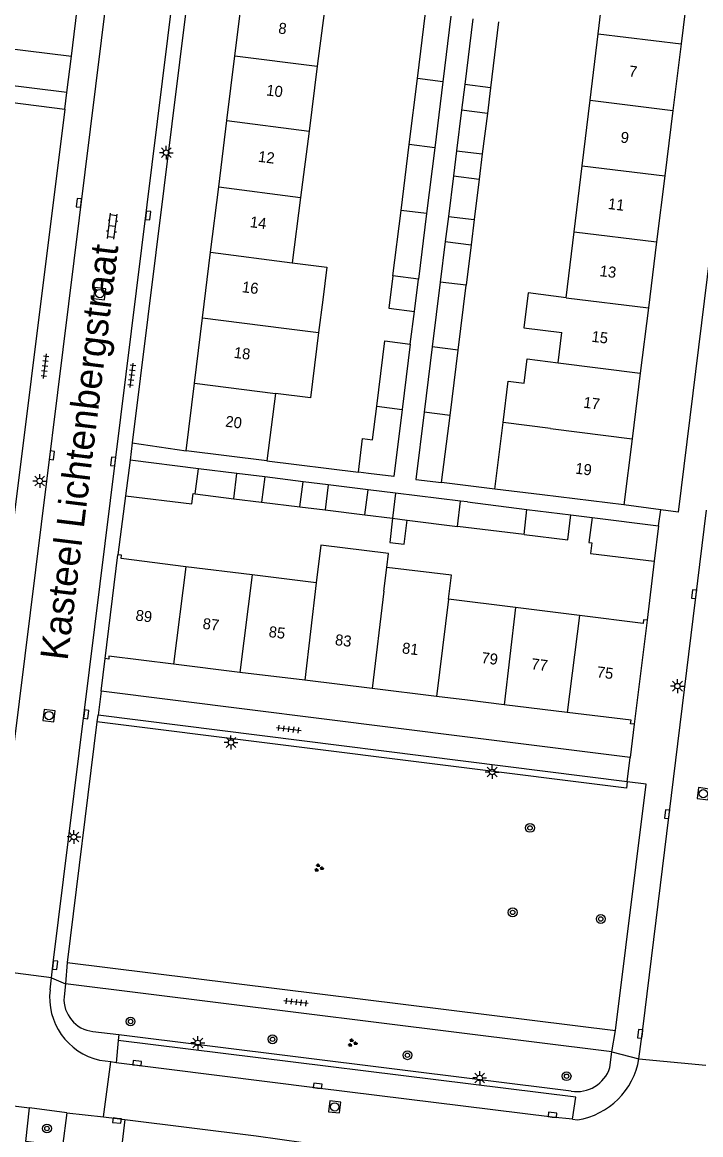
# Model space of a CAD drawing. Extents: x 131000 to 133014, y 396499 to 399001.
# Drawn here: x 131959.6 to 132021.2, y 396746.5 to 396847.4 of the extents above; entities that cross this region are included whole.
import ezdxf

# ---------------------------------------------------------------- set-up
doc = ezdxf.new("R2010")
doc.units = 0
for name, color, linetype in [('gg-afsc-erfafscheiding', 7, 'Continuous'), ('gg-afsc-muur', 7, 'Continuous'), ('gg-anno-huisnummerreeks BGT', 7, 'Continuous'), ('gg-anno-openbare ruimte label', 7, 'Continuous'), ('gg-bbg-bijgebouw', 7, 'Continuous'), ('gg-bbg-gedigitaliseerde bebouwing', 7, 'Continuous'), ('gg-bbg-gedigitaliseerde bijgebouw', 7, 'Continuous'), ('gg-bbg-hoofdgebouw', 7, 'Continuous'), ('gg-bbg-luifel en loopbrug', 7, 'Continuous'), ('gg-bbg-tussenscheiding', 7, 'Continuous'), ('gg-knt-verharding', 7, 'Continuous'), ('gg-knt-verharding nz', 7, 'Continuous'), ('gt-grn-groengrens', 7, 'Continuous'), ('gt-grn-weggrens', 7, 'Continuous'), ('gt-symb-boom', 7, 'Continuous'), ('gt-symb-groenvak', 7, 'Continuous'), ('gt-symb-klinker verharding', 7, 'Continuous'), ('gt-symb-kolk', 7, 'Continuous'), ('gt-symb-lichtmast', 7, 'Continuous'), ('gt-symb-rioolschacht', 7, 'Continuous'), ('gt-symb-tegel verharding', 7, 'Continuous')]:
    doc.layers.add(name, color=color, linetype=linetype)

# ---------------------------------------------------------------- blocks, each defined once
blk = doc.blocks.new('gt0-KOLK')
at = {"layer": 'gt-symb-kolk'}
blk.add_lwpolyline([(0, 0), (0.38, 0), (0.38, 0.4), (-0.38, 0.4), (-0.38, 0), (0, 0)], dxfattribs=at)
blk = doc.blocks.new('gt0-BOOM')
at = {"layer": 'gt-symb-boom'}
for radius in [0.4, 0.2]:
    blk.add_circle((0, 0), radius, dxfattribs=at)
blk = doc.blocks.new('gt0-LMAST')
at = {"layer": 'gt-symb-lichtmast'}
for p, q in [((-0.18, 0.17), (-0.45, 0.44)), ((-0.01, 0.25), (-0.01, 0.62)), ((0.17, 0.17), (0.44, 0.44)), ((-0.26, 0), (-0.63, 0)), ((-0.18, -0.18), (-0.45, -0.45)), ((-0.01, -0.25), (-0.01, -0.63)), ((0.44, -0.45), (0.17, -0.18)), ((0.24, 0), (0.62, 0))]:
    blk.add_line(p, q, dxfattribs=at)
blk.add_circle((-0.01, 0), 0.25, dxfattribs=at)
blk = doc.blocks.new('gt0-RS')
at = {"layer": 'gt-symb-rioolschacht'}
blk.add_lwpolyline([(-0.5, -0.5), (0.5, -0.5), (0.5, 0.5), (-0.5, 0.5)], close=True, dxfattribs=at)
blk.add_circle((0, 0), 0.375, dxfattribs=at)
blk = doc.blocks.new('gt0-TEG1')
at = {"layer": 'gt-symb-tegel verharding'}
for p, q in [((-1.12, 0), (1.12, 0)), ((-0.9, -0.25), (-0.9, 0.25)), ((-0.45, -0.25), (-0.45, 0.25)), ((0, -0.25), (0, 0.25)), ((0.45, -0.25), (0.45, 0.25)), ((0.9, -0.25), (0.9, 0.25))]:
    blk.add_line(p, q, dxfattribs=at)
blk = doc.blocks.new('gt0-GRVAK')
at = {"layer": 'gt-symb-groenvak'}
for p, q in [((-0.11, 0.19), (-0.23, 0.24)), ((-0.18, 0.15), (0.09, 0.15)), ((-0.09, 0.21), (-0.16, 0.32)), ((-0.05, 0.21), (-0.05, 0.39)), ((0, 0.21), (0.06, 0.32)), ((0.02, 0.19), (0.13, 0.24)), ((0.26, -0.05), (0.2, 0.06)), ((0.3, -0.05), (0.3, 0.13)), ((0.35, -0.05), (0.41, 0.06)), ((-0.24, -0.23), (-0.36, -0.18)), ((-0.32, -0.26), (-0.05, -0.26)), ((-0.23, -0.21), (-0.29, -0.09)), ((-0.18, -0.2), (-0.18, -0.02)), ((-0.14, -0.21), (-0.07, -0.09)), ((-0.12, -0.23), (0, -0.18)), ((0.24, -0.07), (0.12, -0.02)), ((0.17, -0.11), (0.44, -0.11)), ((0.37, -0.07), (0.49, -0.02))]:
    blk.add_line(p, q, dxfattribs=at)
blk = doc.blocks.new('gt0-KL1')
at = {"layer": 'gt-symb-klinker verharding'}
for p, q in [((-1.15, 0.3), (1.15, 0.3)), ((-1, -0.3), (-1, 0.3)), ((-0.5, 0.3), (-0.5, 0.45)), ((0, -0.3), (0, 0.3)), ((0.5, 0.3), (0.5, 0.45)), ((1, -0.3), (1, 0.3)), ((-1.15, -0.3), (1.15, -0.3)), ((-0.5, -0.45), (-0.5, -0.3)), ((0.5, -0.45), (0.5, -0.3))]:
    blk.add_line(p, q, dxfattribs=at)

msp = doc.modelspace()

# ---------------------------------------------------------------- linework, layer by layer
at = {"layer": 'gg-afsc-erfafscheiding'}
for p, q in [((131994.82, 396818.22), (131995.19, 396821.17)), ((131981.82, 396807.63), (131990.12, 396806.6)), ((132002.49, 396805.07), (131997.66, 396805.66)), ((132009.38, 396802.73), (132011.31, 396802.49))]:
    msp.add_line(p, q, dxfattribs=at)
at = {"layer": 'gg-afsc-muur'}
for p, q in [((131964.09, 396844.34), (131964.75, 396849.58)), ((131969, 396804.47), (131968.32, 396799.11)), ((132016.93, 396798.53), (132016.28, 396793.17))]:
    msp.add_line(p, q, dxfattribs=at)
at = {"layer": 'gg-bbg-bijgebouw'}
for p, q in [((131963.69, 396841.03), (131964.09, 396844.34)), ((131963.69, 396841.03), (131957.56, 396841.79)), ((131969.41, 396807.68), (131969, 396804.47)), ((131975.61, 396806.91), (131969.41, 396807.68)), ((131979.1, 396806.48), (131975.61, 396806.91)), ((131985.1, 396805.74), (131981.63, 396806.17)), ((131990.99, 396805.01), (131987.37, 396805.46)), ((131999.36, 396803.97), (131993.49, 396804.7)), ((132000, 396803.9), (131999.36, 396803.97)), ((132000, 396803.9), (132005.39, 396803.23)), ((132005.39, 396803.23), (132009.38, 396802.73)), ((132011.31, 396802.49), (132017.33, 396801.75)), ((132017.33, 396801.75), (132016.93, 396798.53))]:
    msp.add_line(p, q, dxfattribs=at)
at = {"layer": 'gg-bbg-gedigitaliseerde bebouwing'}
for p, q in [((132011.85, 396846.35), (132012.57, 396852.26)), ((131987.15, 396849.41), (131986.39, 396843.43)), ((132011.12, 396840.35), (132011.85, 396846.35)), ((131986.39, 396843.43), (131985.64, 396837.52)), ((132010.4, 396834.38), (132011.12, 396840.35)), ((131985.64, 396837.52), (131984.87, 396831.52)), ((132009.68, 396828.4), (132010.4, 396834.38)), ((131984.87, 396831.52), (131984.11, 396825.6)), ((132008.96, 396822.43), (132009.68, 396828.4)), ((131986.89, 396822.23), (131986.51, 396819.26)), ((132008.24, 396816.53), (132008.57, 396819.27)), ((131982.6, 396813.75), (131981.82, 396807.63)), ((132002.49, 396805.07), (132003.24, 396811.12)), ((131981.82, 396807.63), (131974.49, 396808.54)), ((132006.79, 396804.54), (132002.49, 396805.07)), ((132014.19, 396803.63), (132006.79, 396804.54)), ((131974.47, 396798.03), (131968.6, 396798.76)), ((131980.49, 396797.29), (131974.47, 396798.03)), ((131986.3, 396796.56), (131980.49, 396797.29)), ((132004.35, 396794.33), (131998.28, 396795.08)), ((132010.17, 396793.6), (132004.35, 396794.33)), ((132015.92, 396792.89), (132010.17, 396793.6))]:
    msp.add_line(p, q, dxfattribs=at)
for points in [[(131984.11, 396825.6), (131987.26, 396825.21), (131986.89, 396822.23)], [(132008.96, 396822.43), (132005.5, 396822.86), (132005.1, 396819.7), (132008.57, 396819.27)], [(131986.51, 396819.26), (131985.76, 396813.35), (131982.6, 396813.75)], [(132003.24, 396811.12), (132003.7, 396814.87), (132005.15, 396814.69), (132005.41, 396816.88), (132008.24, 396816.53)], [(131992.69, 396797.97), (131992.84, 396799.24), (131986.72, 396799.98), (131986.3, 396796.56)], [(131998.28, 396795.08), (131998.55, 396797.25), (131992.69, 396797.97)]]:
    msp.add_lwpolyline(points, dxfattribs=at)
at = {"layer": 'gg-bbg-gedigitaliseerde bijgebouw'}
for p, q in [((131995.46, 396842.3), (131996.19, 396848.26)), ((131998.51, 396847.96), (131997.77, 396842.01)), ((132000.49, 396847.72), (131999.75, 396841.76)), ((132002.83, 396847.44), (132002.09, 396841.47)), ((131957.97, 396845.08), (131964.09, 396844.34)), ((131994.71, 396836.32), (131995.46, 396842.3)), ((131997.77, 396842.01), (131997.03, 396836.01)), ((132002.09, 396841.47), (131999.75, 396841.76)), ((131999.46, 396839.43), (131999.01, 396835.76)), ((132001.81, 396839.14), (131999.46, 396839.43)), ((132001.81, 396839.14), (132001.35, 396835.47)), ((131993.98, 396830.35), (131994.71, 396836.32)), ((131997.03, 396836.01), (131996.29, 396830.05)), ((131999.01, 396835.76), (132001.35, 396835.47)), ((131998.73, 396833.47), (131998.27, 396829.8)), ((131998.73, 396833.47), (132001.07, 396833.18)), ((132001.07, 396833.18), (132000.61, 396829.51)), ((131993.24, 396824.4), (131993.98, 396830.35)), ((131996.29, 396830.05), (131995.55, 396824.1)), ((131998.27, 396829.8), (132000.61, 396829.51)), ((131997.99, 396827.51), (131997.54, 396823.85)), ((131997.99, 396827.51), (132000.33, 396827.22)), ((132000.33, 396827.22), (131999.88, 396823.55)), ((131995.19, 396821.17), (131995.55, 396824.1)), ((131997.54, 396823.85), (131996.81, 396817.97)), ((131999.15, 396817.68), (131999.88, 396823.55)), ((131991.78, 396812.58), (131992.51, 396818.51)), ((131992.51, 396818.51), (131994.82, 396818.22)), ((131994.82, 396818.22), (131994.09, 396812.29)), ((131996.81, 396817.97), (131996.07, 396812.04)), ((131998.42, 396811.74), (131999.15, 396817.68)), ((131991.4, 396809.55), (131991.78, 396812.58)), ((131997.66, 396805.66), (131998.42, 396811.74)), ((131978.82, 396804.2), (131979.1, 396806.48)), ((131991.02, 396806.49), (131990.12, 396806.6)), ((131981.63, 396806.17), (131981.34, 396803.89)), ((131984.82, 396803.46), (131985.1, 396805.74)), ((131987.37, 396805.46), (131987.09, 396803.18)), ((131975.32, 396804.64), (131978.82, 396804.2)), ((131990.7, 396802.73), (131990.99, 396805.01)), ((131993.49, 396804.7), (131993.22, 396802.42)), ((131981.34, 396803.89), (131984.82, 396803.46)), ((131987.09, 396803.18), (131990.7, 396802.73)), ((131993.22, 396802.42), (131994.55, 396802.26)), ((132011.31, 396802.49), (132011.02, 396800.22)), ((131994.55, 396802.26), (131999.09, 396801.69)), ((132005.13, 396800.95), (131999.09, 396801.69))]:
    msp.add_line(p, q, dxfattribs=at)
for points in [[(131993.24, 396824.4), (131992.88, 396821.47), (131995.19, 396821.17)], [(131994.09, 396812.29), (131993.33, 396806.2), (131991.02, 396806.49)], [(131996.07, 396812.04), (131995.32, 396805.95), (131997.66, 396805.66)], [(131990.12, 396806.6), (131990.5, 396809.66), (131991.4, 396809.55)], [(131969, 396804.47), (131975.02, 396803.72), (131975.14, 396804.66), (131975.32, 396804.64)], [(132005.13, 396800.95), (132009.1, 396800.46), (132009.38, 396802.73)], [(132011.02, 396800.22), (132011.29, 396800.18), (132011.17, 396799.23), (132016.93, 396798.53)]]:
    msp.add_lwpolyline(points, dxfattribs=at)
at = {"layer": 'gg-bbg-hoofdgebouw'}
for p, q in [((132020.1, 396851.32), (132019.37, 396845.45)), ((131978.92, 396844.37), (131979.66, 396850.36)), ((132019.37, 396845.45), (132018.63, 396839.42)), ((131978.19, 396838.5), (131978.92, 396844.37)), ((132018.63, 396839.42), (132017.89, 396833.47)), ((131977.45, 396832.47), (131978.19, 396838.5)), ((132017.89, 396833.47), (132017.15, 396827.48)), ((131976.72, 396826.57), (131977.45, 396832.47)), ((131975.98, 396820.6), (131976.72, 396826.57)), ((132017.15, 396827.48), (132016.41, 396821.51)), ((132016.41, 396821.51), (132015.67, 396815.59)), ((131975.25, 396814.68), (131975.98, 396820.6)), ((132015.67, 396815.59), (132014.93, 396809.62)), ((131974.49, 396808.54), (131975.25, 396814.68)), ((132014.93, 396809.62), (132014.19, 396803.63)), ((131967.16, 396789.69), (131968.32, 396799.11)), ((132016.28, 396793.17), (132015.11, 396783.74)), ((131979.36, 396788.45), (131973.34, 396789.19)), ((131985.25, 396787.73), (131979.36, 396788.45)), ((131991.37, 396786.98), (131985.25, 396787.73)), ((131997.21, 396786.26), (131991.37, 396786.98)), ((132000, 396785.92), (131997.21, 396786.26)), ((132003.32, 396785.51), (132000, 396785.92)), ((132009.04, 396784.81), (132003.32, 396785.51))]:
    msp.add_line(p, q, dxfattribs=at)
for points in [[(131968.6, 396798.76), (131968.64, 396799.07), (131968.32, 396799.11)], [(132016.28, 396793.17), (132015.96, 396793.21), (132015.92, 396792.89)], [(131973.34, 396789.19), (131967.5, 396789.91), (131967.48, 396789.65), (131967.16, 396789.69)], [(132015.11, 396783.74), (132014.79, 396783.78), (132014.83, 396784.1), (132009.04, 396784.81)]]:
    msp.add_lwpolyline(points, dxfattribs=at)
at = {"layer": 'gg-bbg-luifel en loopbrug'}
for p, q in [((131999.75, 396841.76), (131999.46, 396839.43)), ((132002.09, 396841.47), (132001.81, 396839.14)), ((131999.01, 396835.76), (131998.73, 396833.47)), ((132001.35, 396835.47), (132001.07, 396833.18)), ((131998.27, 396829.8), (131997.99, 396827.51)), ((132000.61, 396829.51), (132000.33, 396827.22)), ((131981.63, 396806.17), (131979.1, 396806.48)), ((131987.37, 396805.46), (131985.1, 396805.74)), ((131993.49, 396804.7), (131990.99, 396805.01)), ((131978.82, 396804.2), (131981.34, 396803.89)), ((131984.82, 396803.46), (131987.09, 396803.18)), ((131990.7, 396802.73), (131993.22, 396802.42))]:
    msp.add_line(p, q, dxfattribs=at)
msp.add_lwpolyline([(131993.22, 396802.42), (131992.95, 396800.22), (131994.27, 396800.06), (131994.55, 396802.26)], dxfattribs=at)
at = {"layer": 'gg-bbg-tussenscheiding'}
for p, q in [((132011.85, 396846.35), (132019.37, 396845.45)), ((131978.92, 396844.37), (131986.39, 396843.43)), ((131997.77, 396842.01), (131995.46, 396842.3)), ((132011.12, 396840.35), (132018.63, 396839.42)), ((131978.19, 396838.5), (131985.64, 396837.52)), ((131997.03, 396836.01), (131994.71, 396836.32)), ((132010.4, 396834.38), (132017.89, 396833.47)), ((131977.45, 396832.47), (131984.87, 396831.52)), ((131996.29, 396830.05), (131993.98, 396830.35)), ((132009.68, 396828.4), (132017.15, 396827.48)), ((131976.72, 396826.57), (131984.11, 396825.6)), ((131995.55, 396824.1), (131993.24, 396824.4)), ((131999.88, 396823.55), (131997.54, 396823.85)), ((132008.96, 396822.43), (132016.41, 396821.51)), ((131975.98, 396820.6), (131983.36, 396819.67)), ((131983.36, 396819.67), (131986.51, 396819.26)), ((131999.15, 396817.68), (131996.81, 396817.97)), ((132008.24, 396816.53), (132015.67, 396815.59)), ((131975.25, 396814.68), (131982.6, 396813.75)), ((131991.78, 396812.58), (131994.09, 396812.29)), ((131998.42, 396811.74), (131996.07, 396812.04)), ((132007.52, 396810.57), (132003.24, 396811.12)), ((132007.52, 396810.57), (132014.93, 396809.62)), ((131975.32, 396804.64), (131975.61, 396806.91)), ((131999.09, 396801.69), (131999.36, 396803.97)), ((132005.13, 396800.95), (132005.39, 396803.23)), ((131974.47, 396798.03), (131973.34, 396789.19)), ((131980.49, 396797.29), (131979.36, 396788.45)), ((131992.43, 396795.8), (131992.69, 396797.97)), ((131986.3, 396796.56), (131985.25, 396787.73)), ((131992.43, 396795.8), (131991.37, 396786.98)), ((131998.28, 396795.08), (131997.21, 396786.26)), ((132004.35, 396794.33), (132003.32, 396785.51)), ((132010.17, 396793.6), (132009.04, 396784.81))]:
    msp.add_line(p, q, dxfattribs=at)
at = {"layer": 'gg-knt-verharding'}
for p, q in [((131975.57, 396857.28), (131969.61, 396809.26)), ((131967.97, 396855.16), (131956.33, 396761.52)), ((131958.53, 396840.16), (131963.5, 396839.54)), ((131963.5, 396839.54), (131956.75, 396785.57)), ((131969.61, 396809.26), (131974.49, 396808.54)), ((132017.54, 396803.19), (132014.19, 396803.63)), ((131966.8, 396786.75), (131967.16, 396789.69)), ((132000, 396782.58), (131966.8, 396786.75)), ((132014.49, 396778.53), (131966.53, 396784.56)), ((131966.4, 396783.97), (131963.71, 396762.12)), ((132015.11, 396783.74), (132014.76, 396780.72)), ((132014.76, 396780.72), (132000, 396782.58)), ((131963.71, 396762.12), (132013.43, 396755.96)), ((131962.29, 396760.73), (131956.33, 396761.52)), ((131962.16, 396759.66), (131962.29, 396760.73)), ((131963.57, 396760.2), (131963.43, 396759.01)), ((132013.1, 396754.04), (131963.57, 396760.2)), ((131966.05, 396755.88), (131968.41, 396755.59)), ((131968.35, 396755.07), (131968.16, 396753.04)), ((131968.41, 396755.59), (132009.4, 396750.48)), ((132012.9, 396752.61), (132013.1, 396754.04)), ((131967.67, 396753.12), (131966.65, 396753.26)), ((131967.02, 396748.13), (131967.67, 396753.12)), ((131968.16, 396753.04), (131967.67, 396753.12)), ((131955.36, 396749.55), (131960.3, 396748.95)), ((131963.67, 396748.51), (131960.3, 396748.95)), ((131963.67, 396748.51), (131967.02, 396748.13)), ((132009.53, 396747.91), (132009.98, 396747.86))]:
    msp.add_line(p, q, dxfattribs=at)
for points in [[(132026.48, 396862.86), (132019.12, 396802.99), (132017.54, 396803.19)], [(131962.29, 396760.73), (131962.44, 396762.11), (131974.26, 396857.44)], [(132015.55, 396753.41), (132015.91, 396756.08), (132021.68, 396803.16)], [(131966.53, 396784.56), (131966.48, 396784.57), (131966.4, 396783.97)], [(132013.43, 396755.96), (132016.19, 396778.32), (132014.49, 396778.53)], [(132009.53, 396747.91), (132009.83, 396749.92), (131968.35, 396755.07)], [(131963.67, 396748.51), (131963.28, 396745.47), (131959.96, 396745.9), (131960.3, 396748.95)], [(131967.02, 396748.13), (131968.26, 396747.99), (131968.95, 396747.89)], [(131968.95, 396747.89), (131968.59, 396744.81), (131984.77, 396742.81), (131985.15, 396745.8)], [(131968.95, 396747.89), (131980.85, 396746.41), (131985.15, 396745.8)]]:
    msp.add_lwpolyline(points, dxfattribs=at)
for centre, radius, start, end in [((131967.96, 396758.96), 5.84, 173.1125, 257.0542), ((131966.38, 396758.82), 2.96, 176.2854, 263.5774), ((132008.9, 396754.51), 6.74, 279.2134, 350.5701), ((132009.95, 396753.52), 3.09, 259.8273, 342.9059)]:
    msp.add_arc(centre, radius, start, end, dxfattribs=at)
at = {"layer": 'gg-knt-verharding nz'}
msp.add_lwpolyline([(132009.53, 396747.91), (132007.69, 396748.12), (131986.4, 396750.75), (131968.16, 396753.04)], dxfattribs=at)
at = {"layer": 'gt-grn-groengrens'}
msp.add_lwpolyline([(132014.49, 396778.53), (132014.42, 396777.93), (131966.4, 396783.97)], dxfattribs=at)
at = {"layer": 'gt-grn-weggrens'}
for p, q in [((131963.5, 396839.54), (131963.69, 396841.03)), ((131969.61, 396809.26), (131969.41, 396807.68)), ((132017.33, 396801.75), (132017.54, 396803.19)), ((131966.8, 396786.75), (131966.53, 396784.56)), ((132014.49, 396778.53), (132014.76, 396780.72)), ((131963.71, 396762.12), (131963.57, 396760.2)), ((131962.29, 396760.73), (131963.57, 396760.2)), ((132013.1, 396754.04), (132013.43, 396755.96)), ((131968.41, 396755.59), (131968.35, 396755.07)), ((132013.1, 396754.04), (132015.55, 396753.41)), ((132015.55, 396753.41), (132021.61, 396752.83))]:
    msp.add_line(p, q, dxfattribs=at)

# ---------------------------------------------------------------- block references
at = {"layer": 'gt-symb-boom'}
for p in [(132005.67, 396774.34), (132004.1, 396766.68), (132012.09, 396766.08), (131969.46, 396756.78), (131982.33, 396755.17), (131994.56, 396753.72), (132008.99, 396751.82), (131961.88, 396747.08)]:
    msp.add_blockref('gt0-BOOM', p, dxfattribs=at)
at = {"layer": 'gt-symb-groenvak'}
for p in [(131986.52, 396770.71), (131989.56, 396754.85)]:
    msp.add_blockref('gt0-GRVAK', p, dxfattribs=at)
at = {"layer": 'gt-symb-klinker verharding', "rotation": 82.93185994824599}
msp.add_blockref('gt0-KL1', (131967.8, 396828.91), dxfattribs=at)
at = {"layer": 'gt-symb-kolk'}
for p, rotation in [((131964.97, 396831.01), 82.93185994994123), ((131970.85, 396829.91), -96.7767828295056), ((131962.13, 396808.15), -97.18187853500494), ((131968.07, 396807.55), 82.81812146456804), ((132020.75, 396795.52), 82.99574075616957), ((131965.24, 396784.67), -97.00425924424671), ((132018.3, 396775.56), 83.22321716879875), ((131962.42, 396761.92), -96.48566035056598), ((132015.86, 396755.64), 82.81812146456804), ((131970.03, 396752.81), -7.181878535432), ((131986.4, 396750.75), -7.068140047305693), ((131968.26, 396747.99), 173.45090842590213), ((132007.69, 396748.12), -6.428747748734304)]:
    msp.add_blockref('gt0-KOLK', p, dxfattribs=dict(at, rotation=rotation))
at = {"layer": 'gt-symb-lichtmast'}
for p in [(131972.7, 396835.58), (131961.23, 396805.8), (132019.05, 396787.2), (131978.57, 396782.09), (132002.25, 396779.41), (131964.33, 396773.52), (131975.56, 396754.84), (132001.12, 396751.66)]:
    msp.add_blockref('gt0-LMAST', p, dxfattribs=at)
at = {"layer": 'gt-symb-rioolschacht'}
for p, rotation in [((131966.67, 396822.8), -96.83367234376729), ((131962.07, 396784.53), -96.7767828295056), ((132021.39, 396777.44), -97.64386978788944), ((131987.97, 396749.04), 83.57125225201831)]:
    msp.add_blockref('gt0-RS', p, dxfattribs=dict(at, rotation=rotation))
at = {"layer": 'gt-symb-tegel verharding'}
for p, rotation in [((131961.7, 396816.21), 82.93185994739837), ((131969.57, 396815.39), 82.9318599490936), ((131983.8, 396783.3), -7.0042592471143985), ((131984.46, 396758.54), 173.33703637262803)]:
    msp.add_blockref('gt0-TEG1', p, dxfattribs=dict(at, rotation=rotation))

# ---------------------------------------------------------------- texts
at = {"layer": 'gg-anno-huisnummerreeks BGT'}
for s, rotation, p in [('8', 352.9, (131982.81, 396846.4)), ('7', 352.9, (132014.59, 396842.5)), ('10', 352.9, (131981.72, 396840.78)), ('9', 352.9, (132013.84, 396836.51)), ('12', 352.9, (131980.98, 396834.76)), ('11', 352.9, (132012.7, 396830.48)), ('14', 352.9, (131980.24, 396828.83)), ('13', 352.9, (132011.95, 396824.39)), ('16', 352.9, (131979.52, 396822.93)), ('15', 352.9, (132011.21, 396818.44)), ('18', 352.9, (131978.78, 396816.98)), ('17', 352.9, (132010.47, 396812.46)), ('20', 352.9, (131978.01, 396810.74)), ('19', 352.9, (132009.73, 396806.48)), ('89', 353, (131969.87, 396793.15)), ('87', 353, (131975.95, 396792.4)), ('85', 353, (131981.94, 396791.66)), ('83', 353, (131987.95, 396790.93)), ('81', 353, (131994.03, 396790.18)), ('79', 353, (132001.22, 396789.3)), ('77', 353, (132005.74, 396788.74)), ('75', 353, (132011.69, 396788.01))]:
    msp.add_text(s, height=1, rotation=rotation, dxfattribs=at).set_placement(p)
at = {"layer": 'gg-anno-openbare ruimte label'}
msp.add_text('Kasteel Lichtenbergstraat', height=2.5, rotation=83, dxfattribs=at).set_placement((131963.74, 396789.46))

doc.saveas('drawing.dxf')
